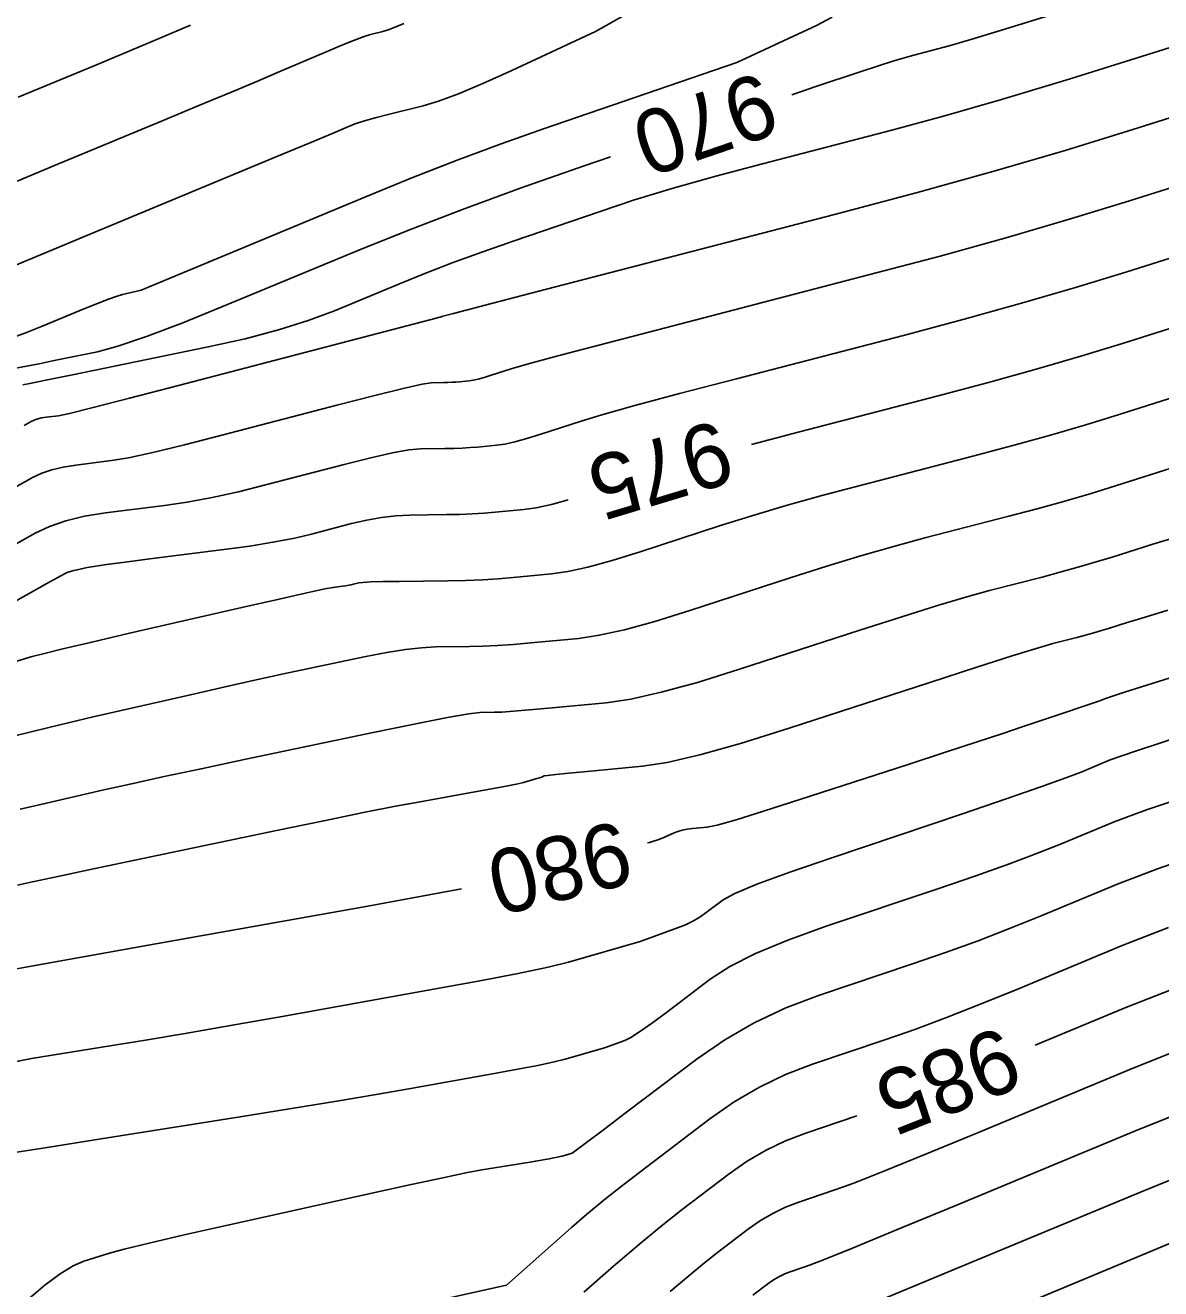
# Model space of a CAD drawing. Extents: x 2175772 to 2185556, y 721391 to 722853.
# Drawn here: x 2178720.3 to 2178770, y 721837.5 to 721892.9 of the extents above; entities that cross this region are included whole.
import ezdxf

# ---------------------------------------------------------------- set-up
doc = ezdxf.new("R2010")
doc.units = 0
doc.layers.add('DT_X_Contour_Major', color=7, linetype='Continuous')
doc.layers.add('DT_X_Contour_Minor', color=7, linetype='Continuous')

msp = doc.modelspace()

# ---------------------------------------------------------------- linework, layer by layer
at = {"layer": 'DT_X_Contour_Major'}
for points in [[(2178752.075, 721874.542), (2178754.183, 721875.098), (2178760.246, 721876.673), (2178762.456, 721877.26), (2178764.539, 721877.839), (2178766.495, 721878.41), (2178768.324, 721878.972), (2178773.033, 721880.462), (2178775.029, 721881.085), (2178777.485, 721881.835), (2178780.403, 721882.713), (2178783.781, 721883.719), (2178793.403, 721886.573), (2178796.681, 721887.547), (2178799.299, 721888.331), (2178801.255, 721888.925), (2178802.552, 721889.327), (2178805.128, 721890.146), (2178806.139, 721890.472), (2178807.241, 721890.834), (2178808.433, 721891.232), (2178809.715, 721891.667), (2178814.572, 721893.323)], [(2178753.843, 721889.869), (2178754.888, 721890.225), (2178756.884, 721890.891), (2178758.315, 721891.352), (2178759.18, 721891.606), (2178760.733, 721892.01), (2178761.681, 721892.281), (2178763.358, 721892.791), (2178765.765, 721893.54)], [(2178719.843, 721877.882), (2178720.307, 721877.969), (2178720.869, 721878.079), (2178721.532, 721878.214), (2178723.43, 721878.604), (2178724.32, 721878.843), (2178725.564, 721879.266), (2178727.162, 721879.875), (2178729.115, 721880.667), (2178734.795, 721883.028), (2178737.015, 721883.924), (2178739.413, 721884.843), (2178741.989, 721885.785), (2178744.743, 721886.75), (2178745.897, 721887.145)], [(2178718.579, 721866.973), (2178721.211, 721868.45), (2178721.684, 721868.713), (2178721.978, 721868.875), (2178722.093, 721868.933), (2178722.161, 721868.954), (2178722.204, 721868.965), (2178722.281, 721868.984), (2178722.392, 721869.011), (2178722.538, 721869.044), (2178722.974, 721869.144), (2178723.268, 721869.196), (2178723.824, 721869.277), (2178724.642, 721869.387), (2178725.723, 721869.525), (2178728.953, 721869.934), (2178730.098, 721870.09), (2178731.11, 721870.253), (2178731.989, 721870.422), (2178732.736, 721870.597), (2178734.549, 721871.072), (2178735.219, 721871.229), (2178735.869, 721871.343), (2178736.498, 721871.414), (2178737.108, 721871.443), (2178738.705, 721871.464), (2178739.288, 721871.476), (2178739.84, 721871.498), (2178740.359, 721871.528), (2178740.847, 721871.568), (2178742.106, 721871.687), (2178742.643, 721871.765), (2178743.308, 721871.914), (2178744.035, 721872.112)], [(2178747.518, 721857.076), (2178747.598, 721857.1), (2178748.017, 721857.236), (2178748.261, 721857.329), (2178748.679, 721857.521), (2178748.847, 721857.586), (2178749.037, 721857.64), (2178749.249, 721857.681), (2178749.483, 721857.71), (2178750.138, 721857.772), (2178750.575, 721857.864), (2178751.395, 721858.095), (2178752.599, 721858.466), (2178754.187, 721858.975), (2178758.932, 721860.517), (2178760.579, 721861.053), (2178761.961, 721861.506), (2178763.08, 721861.875), (2178763.934, 721862.16), (2178765.858, 721862.808), (2178766.498, 721863.025), (2178766.975, 721863.187), (2178767.288, 721863.296), (2178767.438, 721863.351), (2178767.62, 721863.427), (2178768.41, 721863.682), (2178770.645, 721864.391)], [(2178719.139, 721851.434), (2178720.612, 721851.694), (2178722.889, 721852.099), (2178725.972, 721852.65), (2178735.265, 721854.31), (2178738.421, 721854.886), (2178739.368, 721855.068)], [(2178770.827, 721850.791), (2178768.477, 721849.864), (2178764.5, 721848.21)], [(2178756.692, 721845.115), (2178754.447, 721844.359), (2178753.563, 721844.021), (2178752.711, 721843.611), (2178751.889, 721843.13), (2178751.099, 721842.577), (2178749.033, 721841.009), (2178748.183, 721840.342), (2178747.183, 721839.515), (2178746.032, 721838.529), (2178744.732, 721837.385)]]:
    msp.add_lwpolyline(points, dxfattribs=at)
at = {"layer": 'DT_X_Contour_Minor'}
for points in [[(2178720.159, 721877.157), (2178720.459, 721877.214), (2178721.157, 721877.355), (2178722.255, 721877.579), (2178723.751, 721877.886), (2178728.272, 721878.816), (2178729.889, 721879.176), (2178731.35, 721879.561), (2178732.653, 721879.969), (2178733.8, 721880.401), (2178736.649, 721881.585), (2178737.762, 721882.034), (2178738.964, 721882.495), (2178740.256, 721882.968), (2178741.638, 721883.451), (2178745.441, 721884.756), (2178746.955, 721885.254), (2178748.644, 721885.767), (2178750.508, 721886.296), (2178752.548, 721886.841), (2178758.222, 721888.315), (2178760.487, 721888.927), (2178763.027, 721889.655), (2178765.842, 721890.501), (2178768.931, 721891.463), (2178777.537, 721894.186)], [(2178719.626, 721882.314), (2178721.106, 721882.93), (2178723.128, 721883.77), (2178731.273, 721887.153), (2178732.773, 721887.777), (2178733.744, 721888.181), (2178734.187, 721888.367), (2178734.663, 721888.57), (2178734.891, 721888.654), (2178735.216, 721888.754), (2178735.64, 721888.87), (2178736.163, 721889.002), (2178737.687, 721889.376), (2178738.359, 721889.579), (2178739.231, 721889.906), (2178740.303, 721890.358), (2178741.576, 721890.934), (2178745.237, 721892.639), (2178746.516, 721893.355)], [(2178719.721, 721879.231), (2178720.314, 721879.454), (2178720.968, 721879.716), (2178722.796, 721880.468), (2178723.417, 721880.72), (2178723.911, 721880.912), (2178724.278, 721881.043), (2178724.517, 721881.115), (2178725.334, 721881.309), (2178735.128, 721885.379), (2178737.192, 721886.22), (2178739.185, 721886.999), (2178741.107, 721887.715), (2178742.958, 721888.37), (2178751.432, 721891.277), (2178754.925, 721892.903), (2178755.61, 721893.269)], [(2178719.91, 721886.084), (2178721.542, 721886.764), (2178726.222, 721888.708), (2178727.857, 721889.388), (2178729.249, 721889.969), (2178730.399, 721890.453), (2178731.308, 721890.838), (2178733.407, 721891.733), (2178734.121, 721892.033), (2178734.689, 721892.262), (2178735.11, 721892.419), (2178735.384, 721892.504), (2178735.92, 721892.635), (2178736.157, 721892.707), (2178736.464, 721892.822), (2178736.841, 721892.981)], [(2178719.955, 721889.758), (2178723.201, 721891.106), (2178724.382, 721891.598), (2178725.492, 721892.063), (2178726.53, 721892.5), (2178727.496, 721892.911)], [(2178720.208, 721875.371), (2178720.524, 721875.549), (2178720.654, 721875.611), (2178720.804, 721875.662), (2178720.975, 721875.703), (2178721.168, 721875.734), (2178721.708, 721875.802), (2178722.19, 721875.904), (2178723.227, 721876.159), (2178724.822, 721876.566), (2178726.973, 721877.126), (2178738.311, 721880.096), (2178738.424, 721880.119), (2178738.446, 721880.124), (2178738.463, 721880.128), (2178738.476, 721880.132), (2178738.485, 721880.135), (2178738.502, 721880.142), (2178738.509, 721880.144), (2178738.516, 721880.147), (2178738.523, 721880.15), (2178738.532, 721880.153), (2178738.554, 721880.161), (2178739.021, 721880.282), (2178740.403, 721880.642), (2178742.702, 721881.24), (2178745.917, 721882.075), (2178755.711, 721884.621), (2178759.282, 721885.569), (2178762.651, 721886.505), (2178765.816, 721887.429), (2178768.779, 721888.341), (2178776.411, 721890.755)], [(2178719.697, 721872.59), (2178720.612, 721873.104), (2178720.985, 721873.281), (2178721.419, 721873.429), (2178721.913, 721873.548), (2178722.469, 721873.637), (2178724.03, 721873.834), (2178724.776, 721873.96), (2178725.842, 721874.19), (2178727.228, 721874.523), (2178728.935, 721874.96), (2178733.914, 721876.265), (2178735.573, 721876.693), (2178736.815, 721877), (2178737.639, 721877.185), (2178738.046, 721877.248), (2178738.577, 721877.255), (2178738.77, 721877.259), (2178738.953, 721877.266), (2178739.126, 721877.276), (2178739.288, 721877.289), (2178739.706, 721877.329), (2178739.884, 721877.355), (2178740.105, 721877.404), (2178740.369, 721877.476), (2178740.675, 721877.571), (2178741.55, 721877.856), (2178742.239, 721878.053), (2178743.649, 721878.433), (2178745.781, 721878.995), (2178748.635, 721879.74), (2178757.206, 721881.967), (2178760.331, 721882.797), (2178763.276, 721883.615), (2178766.042, 721884.422), (2178768.628, 721885.218), (2178775.285, 721887.324)], [(2178719.187, 721869.809), (2178720.699, 721870.658), (2178721.316, 721870.952), (2178722.034, 721871.197), (2178722.852, 721871.393), (2178723.77, 721871.54), (2178726.352, 721871.866), (2178727.358, 721872.015), (2178728.441, 721872.217), (2178729.6, 721872.471), (2178730.835, 721872.779), (2178734.232, 721873.668), (2178735.396, 721873.961), (2178736.342, 721874.171), (2178737.069, 721874.3), (2178737.577, 721874.346), (2178738.641, 721874.359), (2178739.029, 721874.368), (2178739.396, 721874.382), (2178739.743, 721874.402), (2178740.068, 721874.429), (2178740.906, 721874.508), (2178741.263, 721874.56), (2178741.707, 721874.659), (2178742.236, 721874.804), (2178742.851, 721874.994), (2178744.605, 721875.565), (2178745.524, 721875.841), (2178746.964, 721876.242), (2178748.926, 721876.768), (2178751.409, 721877.419), (2178758.726, 721879.32), (2178761.393, 721880.029), (2178763.908, 721880.727), (2178766.268, 721881.416), (2178768.476, 721882.095), (2178774.159, 721883.893)], [(2178719.788, 721865.01), (2178720.555, 721865.243), (2178721.037, 721865.372), (2178721.909, 721865.586), (2178723.17, 721865.883), (2178724.821, 721866.264), (2178729.742, 721867.393), (2178731.377, 721867.765), (2178732.588, 721868.037), (2178733.376, 721868.208), (2178733.742, 721868.278), (2178734.154, 721868.33), (2178734.3, 721868.35), (2178734.428, 721868.371), (2178734.54, 721868.392), (2178734.636, 721868.415), (2178734.867, 721868.475), (2178735.042, 721868.496), (2178735.396, 721868.514), (2178735.928, 721868.529), (2178736.638, 721868.541), (2178738.769, 721868.568), (2178739.547, 721868.585), (2178740.283, 721868.613), (2178740.976, 721868.654), (2178741.627, 721868.707), (2178743.306, 721868.865), (2178744.022, 721868.971), (2178744.91, 721869.168), (2178745.97, 721869.458), (2178747.202, 721869.84), (2178750.716, 721870.983), (2178752.094, 721871.416), (2178753.594, 721871.859), (2178755.215, 721872.313), (2178756.957, 721872.777), (2178761.766, 721874.026), (2178763.518, 721874.492), (2178765.171, 721874.951), (2178766.722, 721875.403), (2178768.173, 721875.85), (2178771.907, 721877.031)], [(2178719.628, 721861.724), (2178720.57, 721861.966), (2178721.774, 721862.257), (2178723.239, 721862.598), (2178727.494, 721863.574), (2178729.011, 721863.919), (2178730.369, 721864.224), (2178731.57, 721864.487), (2178732.613, 721864.709), (2178735.184, 721865.247), (2178736.097, 721865.425), (2178736.909, 721865.554), (2178737.619, 721865.634), (2178738.227, 721865.665), (2178739.715, 721865.684), (2178740.302, 721865.7), (2178740.946, 721865.732), (2178741.648, 721865.781), (2178742.407, 721865.847), (2178744.507, 721866.044), (2178745.402, 721866.176), (2178746.512, 721866.423), (2178747.837, 721866.786), (2178749.377, 721867.263), (2178753.771, 721868.692), (2178755.379, 721869.204), (2178756.909, 721869.668), (2178758.359, 721870.086), (2178759.732, 721870.456), (2178763.285, 721871.379), (2178764.581, 721871.723), (2178765.802, 721872.062), (2178766.949, 721872.397), (2178768.021, 721872.727), (2178770.781, 721873.6)], [(2178720.033, 721858.554), (2178720.996, 721858.781), (2178723.704, 721859.402), (2178724.854, 721859.66), (2178726.273, 721859.97), (2178727.962, 721860.331), (2178729.92, 721860.743), (2178735.5, 721861.911), (2178737.362, 721862.295), (2178738.76, 721862.57), (2178739.696, 721862.736), (2178740.169, 721862.794), (2178740.813, 721862.802), (2178741.142, 721862.816), (2178741.648, 721862.851), (2178742.329, 721862.908), (2178743.186, 721862.986), (2178745.707, 721863.223), (2178746.781, 721863.381), (2178748.113, 721863.678), (2178749.704, 721864.113), (2178751.552, 721864.686), (2178756.826, 721866.401), (2178758.664, 721866.991), (2178760.224, 721867.477), (2178761.504, 721867.858), (2178762.506, 721868.134), (2178764.805, 721868.732), (2178765.643, 721868.955), (2178766.433, 721869.174), (2178767.175, 721869.391), (2178767.869, 721869.604), (2178769.655, 721870.169), (2178770.963, 721870.569)], [(2178719.914, 721855.229), (2178720.575, 721855.375), (2178721.689, 721855.614), (2178723.255, 721855.945), (2178731.259, 721857.622), (2178733.336, 721858.053), (2178735.077, 721858.407), (2178736.482, 721858.684), (2178737.552, 721858.884), (2178739.958, 721859.314), (2178740.768, 721859.461), (2178741.393, 721859.579), (2178741.834, 721859.669), (2178742.09, 721859.73), (2178742.528, 721859.855), (2178742.676, 721859.897), (2178742.79, 721859.932), (2178742.87, 721859.958), (2178742.917, 721859.976), (2178742.997, 721860.012), (2178743.137, 721860.035), (2178743.496, 721860.076), (2178744.075, 721860.134), (2178744.874, 721860.211), (2178747.296, 721860.439), (2178748.379, 721860.607), (2178749.812, 721860.942), (2178751.595, 721861.442), (2178753.728, 721862.109), (2178759.881, 721864.11), (2178761.949, 721864.779), (2178763.538, 721865.286), (2178764.649, 721865.631), (2178765.28, 721865.813), (2178766.325, 721866.085), (2178766.706, 721866.186), (2178767.065, 721866.286), (2178767.402, 721866.384), (2178767.717, 721866.481), (2178768.529, 721866.738), (2178769.125, 721866.92), (2178770.306, 721867.274)], [(2178718.828, 721847.29), (2178720.535, 721847.637), (2178724.072, 721848.199), (2178725.533, 721848.437), (2178727.261, 721848.729), (2178729.256, 721849.076), (2178731.52, 721849.477), (2178737.912, 721850.619), (2178740.094, 721851.018), (2178741.845, 721851.358), (2178743.165, 721851.639), (2178744.053, 721851.86), (2178747.196, 721852.757), (2178748.833, 721853.351), (2178749.175, 721853.489), (2178749.498, 721853.648), (2178749.804, 721853.827), (2178750.091, 721854.028), (2178750.832, 721854.59), (2178751.341, 721854.864), (2178752.312, 721855.265), (2178753.746, 721855.792), (2178755.642, 721856.445), (2178761.315, 721858.357), (2178763.236, 721859.009), (2178764.744, 721859.531), (2178765.84, 721859.924), (2178766.522, 721860.186), (2178767.791, 721860.714), (2178768.894, 721861.104), (2178771.249, 721861.876)], [(2178719.706, 721843.493), (2178721.212, 721843.734), (2178723.306, 721844.067), (2178729.673, 721845.078), (2178731.926, 721845.439), (2178733.91, 721845.763), (2178735.624, 721846.052), (2178737.068, 721846.304), (2178740.56, 721846.928), (2178741.752, 721847.146), (2178742.708, 721847.332), (2178743.429, 721847.485), (2178743.915, 721847.606), (2178745.631, 721848.096), (2178746.526, 721848.42), (2178746.783, 721848.55), (2178747.173, 721848.798), (2178747.694, 721849.165), (2178748.347, 721849.651), (2178750.265, 721851.106), (2178751.122, 721851.66), (2178752.254, 721852.231), (2178753.661, 721852.819), (2178755.344, 721853.424), (2178760.198, 721855.059), (2178761.901, 721855.642), (2178763.37, 721856.163), (2178764.605, 721856.623), (2178765.606, 721857.021), (2178767.963, 721858.002), (2178769.377, 721858.526), (2178771.853, 721859.362)], [(2178720.34, 721837.044), (2178721.112, 721837.692), (2178721.784, 721838.191), (2178722.356, 721838.544), (2178722.828, 721838.749), (2178723.952, 721839.1), (2178724.596, 721839.277), (2178725.684, 721839.542), (2178727.215, 721839.897), (2178729.191, 721840.34), (2178735.052, 721841.643), (2178737.026, 721842.078), (2178738.553, 721842.408), (2178739.633, 721842.631), (2178740.265, 721842.749), (2178741.74, 721842.984), (2178742.079, 721843.039), (2178742.371, 721843.088), (2178742.616, 721843.131), (2178743.208, 721843.237), (2178743.41, 721843.274), (2178743.572, 721843.305), (2178743.694, 721843.331), (2178743.776, 721843.352), (2178744.067, 721843.435), (2178744.219, 721843.49), (2178744.392, 721843.61), (2178744.847, 721843.948), (2178745.585, 721844.502), (2178746.604, 721845.274), (2178749.698, 721847.622), (2178750.902, 721848.456), (2178752.195, 721849.197), (2178753.576, 721849.846), (2178755.045, 721850.402), (2178759.08, 721851.762), (2178760.565, 721852.275), (2178761.996, 721852.795), (2178763.37, 721853.322), (2178764.69, 721853.856), (2178768.134, 721855.289), (2178769.861, 721855.948), (2178772.457, 721856.847)], [(2178770.344, 721853.369), (2178768.306, 721852.577), (2178763.774, 721850.691), (2178762.136, 721850.022), (2178760.621, 721849.428), (2178759.23, 721848.908), (2178757.962, 721848.464), (2178754.746, 721847.381), (2178753.561, 721846.926), (2178752.417, 721846.377), (2178751.315, 721845.731), (2178750.254, 721844.99), (2178747.482, 721842.887), (2178746.497, 721842.129), (2178745.618, 721841.432), (2178744.847, 721840.797), (2178744.184, 721840.224), (2178741.339, 721837.692), (2178734.175, 721836.1)], [(2178771.311, 721848.213), (2178768.649, 721847.152), (2178761.941, 721844.361), (2178759.667, 721843.421), (2178757.873, 721842.692), (2178756.559, 721842.175), (2178755.727, 721841.87), (2178754.148, 721841.338), (2178753.566, 721841.115), (2178753.005, 721840.845), (2178752.464, 721840.528), (2178751.944, 721840.164), (2178750.583, 721839.132), (2178750.013, 721838.683), (2178749.324, 721838.112), (2178748.516, 721837.418)], [(2178771.794, 721845.635), (2178768.82, 721844.439), (2178761.025, 721841.196), (2178758.432, 721840.12), (2178756.498, 721839.324), (2178755.224, 721838.808), (2178754.609, 721838.572), (2178753.849, 721838.316), (2178753.569, 721838.209), (2178753.299, 721838.079), (2178753.039, 721837.926), (2178752.788, 721837.751), (2178752.133, 721837.254)], [(2178772.343, 721843.084), (2178769.107, 721841.775), (2178760.379, 721838.144), (2178757.509, 721836.95)], [(2178770.884, 721839.73), (2178763.209, 721836.537)]]:
    msp.add_lwpolyline(points, dxfattribs=at)

# ---------------------------------------------------------------- texts
at = {"layer": 'DT_X_Contour_Major'}
for s, rotation, p in [('970', 198.9162, (2178752.544, 721890.905)), ('975', 196.8124, (2178750.681, 721875.651)), ('980', 193.8361, (2178746.375, 721858.085)), ('985', 201.6174, (2178763.083, 721849.091))]:
    msp.add_text(s, height=2.8, rotation=rotation, dxfattribs=at).set_placement(p)

doc.saveas('drawing.dxf')
